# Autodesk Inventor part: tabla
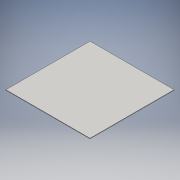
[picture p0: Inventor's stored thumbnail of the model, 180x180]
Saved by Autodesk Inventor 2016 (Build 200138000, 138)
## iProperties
Created: 2016-06
Part Number: tabla
Material: Genérico
Document SubType Name: Modeling
Designer: adm
Density: 1 g/cm^3
Appearance: Valor por defecto
Author: adm
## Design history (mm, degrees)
sketch "Boceto1"
  geometry: L1 (-400, -400)-(400, -400); L2 (400, -400)-(400, 400); L3 (400, 400)-(-400, 400); L4 (-400, 400)-(-400, -400); L5 (-400, -400)-(400, 400); L6 (400, -400)-(-400, 400); 1 further point
  constraints: 12 end point, 2 midpoint, 2 parallel, 1 horizontal, 1 perpendicular
  dimensions: "d0" = 800 distance of L3.end L2.end; "d1" = 800 distance of L2.end L1.end
extrude "Extrusión1" new body sketch "Boceto1" distance "d2" = 5; taper "d3" = 0 deg
node "Sólido1"
